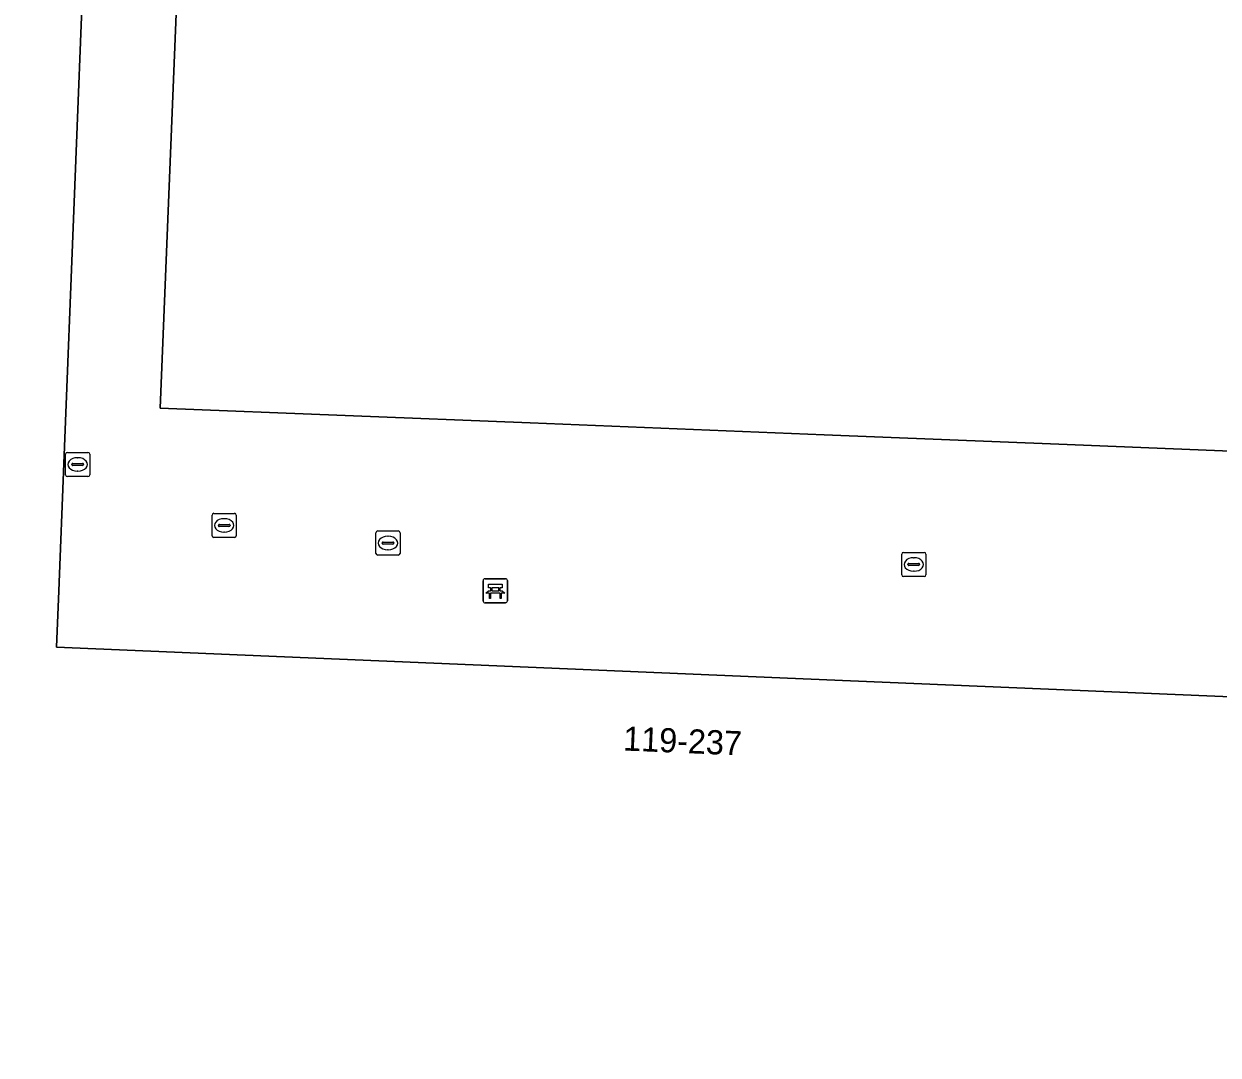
# Model space of a CAD drawing. Extents: x 160888 to 161385, y 386490 to 386908.
# Drawn here: x 161040.48 to 161089.85, y 386535.71 to 386578.36 of the extents above; entities that cross this region are included whole.
import ezdxf

# ---------------------------------------------------------------- set-up
doc = ezdxf.new("R2010")
doc.units = 0
for name, color, linetype in [('IMGEO_Bank', 7, 'Continuous'), ('IMGEO_Kolk', 7, 'Continuous'), ('IMGEO_Pand', 7, 'Continuous'), ('IMGEO_Pand_nummerreeks', 7, 'Continuous'), ('IMGEO_Rioolput', 7, 'Continuous'), ('IMGEO_Voetgangersgebied_open', 7, 'Continuous')]:
    doc.layers.add(name, color=color, linetype=linetype)

msp = doc.modelspace()

# ---------------------------------------------------------------- linework, layer by layer
at = {"layer": 'IMGEO_Bank'}
for p, q in [((161059.471, 386554.487), (161059.471, 386555.328)), ((161059.471, 386555.328), (161059.471, 386554.487)), ((161059.546, 386555.412), (161060.387, 386555.412)), ((161060.387, 386555.412), (161059.546, 386555.412)), ((161059.78, 386554.918), (161059.78, 386555.024)), ((161059.824, 386555.024), (161059.824, 386554.918)), ((161060.112, 386555.03), (161059.83, 386555.03)), ((161060.118, 386554.918), (161060.118, 386555.024)), ((161060.162, 386555.024), (161060.162, 386554.918)), ((161060.471, 386555.337), (161060.471, 386554.496)), ((161060.471, 386554.496), (161060.471, 386555.337)), ((161060.168, 386554.81), (161059.775, 386554.81)), ((161059.83, 386554.912), (161060.112, 386554.912)), ((161060.396, 386554.412), (161059.555, 386554.412)), ((161059.555, 386554.412), (161060.396, 386554.412))]:
    msp.add_line(p, q, dxfattribs=at)
for points in [[(161059.774, 386555.03), (161059.688, 386555.03), (161059.688, 386555.191), (161060.251, 386555.191), (161060.251, 386555.03), (161060.168, 386555.03)], [(161059.718, 386554.81), (161059.576, 386554.81), (161059.688, 386554.912), (161059.774, 386554.912)], [(161059.768, 386554.803), (161059.768, 386554.596), (161059.725, 386554.596), (161059.725, 386554.803)], [(161060.168, 386554.912), (161060.251, 386554.912), (161060.363, 386554.81), (161060.224, 386554.81)], [(161060.218, 386554.803), (161060.218, 386554.596), (161060.174, 386554.596), (161060.174, 386554.803)]]:
    msp.add_lwpolyline(points, dxfattribs=at)
for centre, radius, start, end in [((161059.549, 386555.334), 0.0779, 92.4484, 184.2845), ((161059.549, 386555.334), 0.0779, 92.4484, 184.2845), ((161059.773, 386555.023), 0.00671, 2.8957, 87.1043), ((161059.83, 386555.023), 0.00671, 92.8957, 177.1043), ((161060.112, 386555.023), 0.00671, 2.8957, 87.1043), ((161060.169, 386555.023), 0.00671, 92.8957, 177.1043), ((161060.393, 386555.334), 0.0779, 2.4484, 94.2845), ((161060.393, 386555.334), 0.0779, 2.4484, 94.2845), ((161059.718, 386554.803), 0.00671, 2.8957, 87.1043), ((161059.775, 386554.803), 0.00671, 92.8957, 177.1043), ((161059.773, 386554.919), 0.00671, 272.8957, 357.1043), ((161059.83, 386554.919), 0.00671, 182.8957, 267.1043), ((161060.112, 386554.919), 0.00671, 272.8957, 357.1043), ((161060.169, 386554.919), 0.00671, 182.8957, 267.1043), ((161060.167, 386554.803), 0.00671, 2.8957, 87.1043), ((161060.224, 386554.803), 0.00671, 92.8957, 177.1043), ((161059.549, 386554.49), 0.0779, 182.4484, 274.2845), ((161059.549, 386554.49), 0.0779, 182.4484, 274.2845), ((161060.393, 386554.49), 0.0779, 272.4484, 4.2845), ((161060.393, 386554.49), 0.0779, 272.4484, 4.2845)]:
    msp.add_arc(centre, radius, start, end, dxfattribs=at)
at = {"layer": 'IMGEO_Kolk'}
for p, q in [((161055.035, 386556.459), (161055.035, 386557.311)), ((161055.11, 386557.385), (161055.962, 386557.385)), ((161055.523, 386557.165), (161055.548, 386557.165)), ((161056.036, 386557.311), (161056.036, 386556.459)), ((161055.294, 386556.879), (161055.294, 386556.891)), ((161055.732, 386556.842), (161055.334, 386556.842)), ((161055.337, 386556.928), (161055.735, 386556.928)), ((161055.546, 386556.605), (161055.521, 386556.605)), ((161055.778, 386556.891), (161055.778, 386556.879)), ((161076.844, 386556.5), (161077.696, 386556.5)), ((161055.962, 386556.385), (161055.11, 386556.385)), ((161076.769, 386555.574), (161076.769, 386556.426)), ((161077.028, 386555.994), (161077.028, 386556.006)), ((161077.071, 386556.043), (161077.469, 386556.043)), ((161077.257, 386556.28), (161077.282, 386556.28)), ((161077.512, 386556.006), (161077.512, 386555.994)), ((161077.77, 386556.426), (161077.77, 386555.574)), ((161077.696, 386555.5), (161076.844, 386555.5)), ((161077.466, 386555.957), (161077.068, 386555.957)), ((161077.28, 386555.72), (161077.255, 386555.72))]:
    msp.add_line(p, q, dxfattribs=at)
for points in [[(161055.035, 386556.459), (161055.035, 386557.311)], [(161055.11, 386557.385), (161055.962, 386557.385)], [(161056.036, 386557.311), (161056.036, 386556.459)], [(161076.844, 386556.5), (161077.696, 386556.5)], [(161055.962, 386556.385), (161055.11, 386556.385)], [(161076.769, 386555.574), (161076.769, 386556.426)], [(161077.77, 386556.426), (161077.77, 386555.574)], [(161077.696, 386555.5), (161076.844, 386555.5)]]:
    msp.add_lwpolyline(points, dxfattribs=at)
for centre, radius, start, end in [((161055.112, 386557.309), 0.0765, 91.552, 178.448), ((161055.112, 386557.309), 0.0765, 91.552, 178.448), ((161055.96, 386557.309), 0.0765, 1.552, 88.448), ((161055.96, 386557.309), 0.0765, 1.552, 88.448), ((161055.334, 386556.888), 0.0403, 85.8775, 175.7526), ((161055.331, 386556.878), 0.0366, 178.938, 274.7102), ((161055.735, 386556.885), 0.043, 264.8664, 352.4533), ((161055.739, 386556.89), 0.0386, 1.7309, 96.639), ((161076.846, 386556.424), 0.0765, 91.552, 178.448), ((161076.846, 386556.424), 0.0765, 91.552, 178.448), ((161077.694, 386556.424), 0.0765, 1.552, 88.448), ((161077.694, 386556.424), 0.0765, 1.552, 88.448), ((161055.112, 386556.461), 0.0765, 181.552, 268.448), ((161055.112, 386556.461), 0.0765, 181.552, 268.448), ((161055.96, 386556.461), 0.0765, 271.552, 358.448), ((161055.96, 386556.461), 0.0765, 271.552, 358.448), ((161077.068, 386556.003), 0.0403, 85.8775, 175.7526), ((161077.065, 386555.993), 0.0366, 178.938, 274.7102), ((161077.469, 386556), 0.043, 264.8664, 352.4533), ((161077.473, 386556.005), 0.0386, 1.7309, 96.639), ((161076.846, 386555.576), 0.0765, 181.552, 268.448), ((161076.846, 386555.576), 0.0765, 181.552, 268.448), ((161077.694, 386555.576), 0.0765, 271.552, 358.448), ((161077.694, 386555.576), 0.0765, 271.552, 358.448)]:
    msp.add_arc(centre, radius, start, end, dxfattribs=at)
for centre, major_axis, ratio, start_param, end_param in [((161055.522, 386556.885), (-0.387, 0.002), 0.722429, 4.712389, 7.853982), ((161055.547, 386556.885), (-0.39, 0.002), 0.717154, 1.570796, 4.712389), ((161077.256, 386556), (-0.387, 0.002), 0.722429, 4.712389, 7.853982), ((161077.281, 386556), (-0.39, 0.002), 0.717154, 1.570796, 4.712389)]:
    msp.add_ellipse(centre, major_axis=major_axis, ratio=ratio, start_param=start_param, end_param=end_param, dxfattribs=at)
at = {"layer": 'IMGEO_Pand'}
for points in [[(161046.888, 386581.503), (161046.117, 386562.468), (161061.417, 386561.851), (161073.561, 386561.361), (161083.268, 386560.969), (161090.381, 386560.682), (161128.539, 386559.143), (161129.239, 386576.285), (161129.528, 386583.353)], [(161002.953, 386513.11), (161051.083, 386511.057), (161051.206, 386511.052), (161052.017, 386528.899), (161080.022, 386527.764), (161080.132, 386529.382), (161081.504, 386529.308), (161086.537, 386529.035), (161086.775, 386534.825), (161095.779, 386534.461), (161095.797, 386534.862), (161094.798, 386534.906), (161094.918, 386537.567), (161096.112, 386537.502), (161096.134, 386538.109), (161095.807, 386538.111), (161096.256, 386550.282), (161074.659, 386551.192), (161041.832, 386552.576), (161041.925, 386554.908), (161042.136, 386560.18), (161042.986, 386581.802), (161011.368, 386583.058)]]:
    msp.add_lwpolyline(points, dxfattribs=at)
at = {"layer": 'IMGEO_Rioolput'}
for p, q in [((161042.207, 386559.71), (161042.207, 386560.562)), ((161042.282, 386560.636), (161043.134, 386560.636)), ((161043.208, 386560.562), (161043.208, 386559.71)), ((161042.466, 386560.13), (161042.466, 386560.142)), ((161042.904, 386560.093), (161042.506, 386560.093)), ((161042.509, 386560.179), (161042.907, 386560.179)), ((161042.695, 386560.416), (161042.72, 386560.416)), ((161042.95, 386560.142), (161042.95, 386560.13)), ((161043.134, 386559.636), (161042.282, 386559.636)), ((161042.718, 386559.856), (161042.693, 386559.856)), ((161048.264, 386557.188), (161048.264, 386558.04)), ((161048.339, 386558.114), (161049.191, 386558.114)), ((161049.265, 386558.04), (161049.265, 386557.188)), ((161048.523, 386557.608), (161048.523, 386557.62)), ((161048.961, 386557.571), (161048.563, 386557.571)), ((161048.566, 386557.657), (161048.964, 386557.657)), ((161048.752, 386557.894), (161048.777, 386557.894)), ((161049.007, 386557.62), (161049.007, 386557.608)), ((161049.191, 386557.114), (161048.339, 386557.114)), ((161048.775, 386557.334), (161048.75, 386557.334))]:
    msp.add_line(p, q, dxfattribs=at)
for points in [[(161042.207, 386559.71), (161042.207, 386560.562)], [(161042.282, 386560.636), (161043.134, 386560.636)], [(161043.208, 386560.562), (161043.208, 386559.71)], [(161043.134, 386559.636), (161042.282, 386559.636)], [(161048.264, 386557.188), (161048.264, 386558.04)], [(161048.339, 386558.114), (161049.191, 386558.114)], [(161049.265, 386558.04), (161049.265, 386557.188)], [(161049.191, 386557.114), (161048.339, 386557.114)]]:
    msp.add_lwpolyline(points, dxfattribs=at)
for centre, radius, start, end in [((161042.284, 386560.56), 0.0765, 91.552, 178.448), ((161042.284, 386560.56), 0.0765, 91.552, 178.448), ((161043.132, 386560.56), 0.0765, 1.552, 88.448), ((161043.132, 386560.56), 0.0765, 1.552, 88.448), ((161042.506, 386560.139), 0.0403, 85.8775, 175.7526), ((161042.503, 386560.129), 0.0366, 178.938, 274.7102), ((161042.907, 386560.136), 0.043, 264.8664, 352.4533), ((161042.911, 386560.141), 0.0386, 1.7309, 96.639), ((161042.284, 386559.712), 0.0765, 181.552, 268.448), ((161042.284, 386559.712), 0.0765, 181.552, 268.448), ((161043.132, 386559.712), 0.0765, 271.552, 358.448), ((161043.132, 386559.712), 0.0765, 271.552, 358.448), ((161048.341, 386558.038), 0.0765, 91.552, 178.448), ((161048.341, 386558.038), 0.0765, 91.552, 178.448), ((161049.189, 386558.038), 0.0765, 1.552, 88.448), ((161049.189, 386558.038), 0.0765, 1.552, 88.448), ((161048.563, 386557.617), 0.0403, 85.8775, 175.7526), ((161048.56, 386557.607), 0.0366, 178.938, 274.7102), ((161048.964, 386557.614), 0.043, 264.8664, 352.4533), ((161048.968, 386557.619), 0.0386, 1.7309, 96.639), ((161048.341, 386557.19), 0.0765, 181.552, 268.448), ((161048.341, 386557.19), 0.0765, 181.552, 268.448), ((161049.189, 386557.19), 0.0765, 271.552, 358.448), ((161049.189, 386557.19), 0.0765, 271.552, 358.448)]:
    msp.add_arc(centre, radius, start, end, dxfattribs=at)
for centre, major_axis, ratio, start_param, end_param in [((161042.694, 386560.136), (-0.387, 0.002), 0.722429, 4.712389, 7.853982), ((161042.719, 386560.136), (-0.39, 0.002), 0.717154, 1.570796, 4.712389), ((161048.751, 386557.614), (-0.387, 0.002), 0.722429, 4.712389, 7.853982), ((161048.776, 386557.614), (-0.39, 0.002), 0.717154, 1.570796, 4.712389)]:
    msp.add_ellipse(centre, major_axis=major_axis, ratio=ratio, start_param=start_param, end_param=end_param, dxfattribs=at)
at = {"layer": 'IMGEO_Voetgangersgebied_open'}
for points in [[(161042.986, 386581.802), (161042.136, 386560.18), (161041.925, 386554.908), (161041.832, 386552.576), (161074.659, 386551.192), (161096.256, 386550.282), (161095.807, 386538.111), (161096.134, 386538.109), (161096.112, 386537.502), (161094.918, 386537.567), (161094.798, 386534.906), (161095.797, 386534.862), (161095.779, 386534.461), (161086.775, 386534.825), (161086.537, 386529.035), (161081.504, 386529.308), (161080.132, 386529.382), (161080.022, 386527.764), (161052.017, 386528.899), (161051.206, 386511.052), (161051.083, 386511.057), (161051.677, 386507.711), (161054.692, 386507.633), (161095.632, 386509.131)], [(161143.412, 386571.685), (161139.877, 386568.704), (161131.001, 386561.219), (161128.539, 386559.143), (161090.381, 386560.682), (161083.268, 386560.969), (161073.561, 386561.361), (161061.417, 386561.851), (161046.117, 386562.468), (161046.888, 386581.503)]]:
    msp.add_lwpolyline(points, dxfattribs=at)

# ---------------------------------------------------------------- texts
at = {"layer": 'IMGEO_Pand_nummerreeks'}
msp.add_text('119-237', height=1, rotation=357.5864, dxfattribs=at).set_placement((161065.242, 386548.306))

doc.saveas('drawing.dxf')
